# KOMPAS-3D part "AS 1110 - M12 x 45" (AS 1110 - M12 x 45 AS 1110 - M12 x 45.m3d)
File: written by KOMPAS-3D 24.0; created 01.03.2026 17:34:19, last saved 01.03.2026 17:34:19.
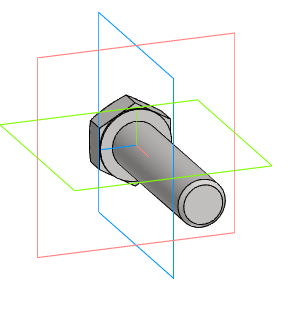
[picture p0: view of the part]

Document properties: Автор: R2D2; Полное имя файла: E:\Работа\Зайцев\GVWR3131M-2W-F-S Задвижка клиновая с выдвижным штоком DN.ru Ду50-200 Ру63\DN50\исходные материалы\AS 1110 - M12 x 45 AS 1110 - M12 x 45.m3d

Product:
- Body: Solid1  | qty 1
- Part/product: AS 1110 - M12 x 45
    Комментарий: Болты и винты   шестигранные точные   метрические ISO
    additional columns: Сталь, мягкая

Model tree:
1. Solid1  (labels: Solid1)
